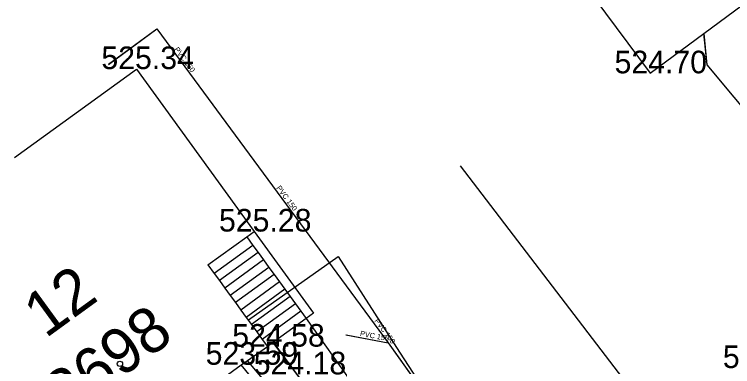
# Model space of a CAD drawing. Extents: x -668867 to -667827, y -1131943 to -1131019.
# Drawn here: x -668667.52 to -668643.7, y -1131500.87 to -1131489.18 of the extents above; entities that cross this region are included whole.
import ezdxf

# ---------------------------------------------------------------- set-up
doc = ezdxf.new("R2010")
doc.units = 0
for name, color, linetype in [('G_Bod_tecka', 7, 'Continuous'), ('G_Bod_vyska', 7, 'Continuous'), ('G_Budovy-znacky', 7, 'Continuous'), ('G_Budovy_Objekty', 7, 'Continuous'), ('G_Budovy_vstupy', 7, 'Continuous'), ('G_Cesty_Schody', 7, 'Continuous'), ('G_Cisla_orientacni', 7, 'Continuous'), ('G_Cisla_popisna', 7, 'Continuous'), ('G_Plochy_zpevnene', 7, 'Continuous'), ('G_Ploty', 7, 'Continuous'), ('G_Z_KANAL_podz_kotovane', 7, 'Continuous'), ('G_Z_KANAL_podz_priblizne', 7, 'Continuous'), ('G_Z_SPOJE_podz_geodeticky', 7, 'Continuous'), ('G_Z_SPOJE_podz_kotovane', 7, 'Continuous'), ('G_Z_SPOJE_podz_priblizne', 7, 'Continuous'), ('G_Z_VODA_podz_kotovane', 7, 'Continuous'), ('Vrstva 12', 7, 'Continuous'), ('Vrstva 17', 7, 'Continuous'), ('Vrstva 25', 7, 'Continuous'), ('Vrstva 3', 7, 'Continuous')]:
    doc.layers.add(name, color=color, linetype=linetype)

msp = doc.modelspace()

# ---------------------------------------------------------------- linework, layer by layer
at = {"layer": 'G_Bod_tecka'}
for p, q in [((-668663.47, -1131491), (-668663.47, -1131491)), ((-668646.43, -1131491.14), (-668646.43, -1131491.14)), ((-668659.57, -1131496.39), (-668659.57, -1131496.39)), ((-668659.13, -1131500.21), (-668659.13, -1131500.21)), ((-668660.01, -1131500.81), (-668660.01, -1131500.81))]:
    msp.add_line(p, q, dxfattribs=at)
at = {"layer": 'G_Budovy-znacky'}
msp.add_circle((-668664.02, -1131500.78), 0.0875, dxfattribs=at)
at = {"layer": 'G_Budovy_Objekty'}
for p, q in [((-668649.42, -1131487.12), (-668646.43, -1131491.14)), ((-668646.43, -1131491.14), (-668643.03, -1131488.6)), ((-668667.52, -1131493.93), (-668663.47, -1131491)), ((-668663.47, -1131491), (-668659.57, -1131496.39)), ((-668661.1, -1131497.5), (-668659.81, -1131496.57)), ((-668659.81, -1131496.57), (-668659.57, -1131496.39)), ((-668661.1, -1131497.5), (-668660.89, -1131497.78)), ((-668660.89, -1131497.78), (-668660.72, -1131498.02)), ((-668660.72, -1131498.02), (-668660.54, -1131498.27)), ((-668660.54, -1131498.27), (-668660.36, -1131498.51)), ((-668660.36, -1131498.51), (-668660.19, -1131498.75)), ((-668660.19, -1131498.75), (-668660.01, -1131499)), ((-668660.01, -1131499), (-668659.83, -1131499.24)), ((-668659.83, -1131499.24), (-668659.66, -1131499.48)), ((-668659.66, -1131499.48), (-668659.48, -1131499.72)), ((-668659.48, -1131499.72), (-668659.3, -1131499.97)), ((-668659.3, -1131499.97), (-668659.13, -1131500.21)), ((-668659.79, -1131500.67), (-668659.13, -1131500.21)), ((-668660, -1131500.81), (-668659.79, -1131500.67))]:
    msp.add_line(p, q, dxfattribs=at)
at = {"layer": 'G_Budovy_vstupy'}
msp.add_line((-668661.98, -1131502.26), (-668660, -1131500.81), dxfattribs=at)
at = {"layer": 'G_Cesty_Schody'}
for p, q in [((-668659.81, -1131496.57), (-668659.61, -1131496.85)), ((-668659.57, -1131496.39), (-668657.6, -1131499.1)), ((-668659.61, -1131496.85), (-668660.89, -1131497.78)), ((-668659.61, -1131496.85), (-668659.43, -1131497.09)), ((-668659.43, -1131497.09), (-668660.72, -1131498.02)), ((-668659.43, -1131497.09), (-668659.26, -1131497.33)), ((-668659.26, -1131497.33), (-668660.54, -1131498.27)), ((-668659.26, -1131497.33), (-668659.08, -1131497.58)), ((-668659.08, -1131497.58), (-668660.36, -1131498.51)), ((-668659.08, -1131497.58), (-668658.9, -1131497.82)), ((-668658.9, -1131497.82), (-668660.19, -1131498.75)), ((-668658.9, -1131497.82), (-668658.73, -1131498.06)), ((-668658.73, -1131498.06), (-668660.01, -1131499)), ((-668658.73, -1131498.06), (-668658.55, -1131498.3)), ((-668658.55, -1131498.3), (-668659.83, -1131499.24)), ((-668658.55, -1131498.3), (-668658.37, -1131498.55)), ((-668658.37, -1131498.55), (-668659.66, -1131499.48)), ((-668658.37, -1131498.55), (-668658.2, -1131498.79)), ((-668658.2, -1131498.79), (-668659.48, -1131499.72)), ((-668658.2, -1131498.79), (-668658.02, -1131499.03)), ((-668658.02, -1131499.03), (-668659.3, -1131499.97)), ((-668658.02, -1131499.03), (-668657.84, -1131499.28)), ((-668657.6, -1131499.1), (-668657.84, -1131499.28)), ((-668657.84, -1131499.28), (-668659.13, -1131500.21))]:
    msp.add_line(p, q, dxfattribs=at)
at = {"layer": 'G_Plochy_zpevnene'}
for p, q in [((-668657.84, -1131499.28), (-668651.99, -1131507.5)), ((-668659.25, -1131501.71), (-668660, -1131500.81)), ((-668659.25, -1131501.32), (-668659.79, -1131500.67))]:
    msp.add_line(p, q, dxfattribs=at)
at = {"layer": 'G_Ploty'}
msp.add_line((-668646.1, -1131502.88), (-668652.73, -1131494.21), dxfattribs=at)
at = {"layer": 'G_Z_KANAL_podz_kotovane'}
msp.add_line((-668656.52, -1131499.82), (-668655.12, -1131500.08), dxfattribs=at)
msp.add_lwpolyline([(-668664.4, -1131490.84), (-668662.8, -1131489.66), (-668655.12, -1131500.08), (-668650.54, -1131506.52)], dxfattribs=at)
at = {"layer": 'G_Z_KANAL_podz_priblizne'}
msp.add_lwpolyline([(-668644.66, -1131489.82), (-668644.55, -1131490.86), (-668640.92, -1131495.22), (-668640.78, -1131496), (-668639.75, -1131497.44)], dxfattribs=at)
at = {"layer": 'G_Z_SPOJE_podz_geodeticky'}
msp.add_lwpolyline([(-668659.76, -1131499.32), (-668656.78, -1131497.22), (-668654.75, -1131500.39), (-668650.81, -1131506.44), (-668650.86, -1131507.14), (-668653.05, -1131508.79), (-668656.45, -1131511.14), (-668656.9, -1131511.45), (-668657.68, -1131511.93), (-668658.58, -1131512.67), (-668663.292, -1131516.083)], dxfattribs=at)
at = {"layer": 'G_Z_SPOJE_podz_kotovane'}
msp.add_lwpolyline([(-668659.76, -1131499.32), (-668656.78, -1131497.22), (-668654.75, -1131500.39), (-668650.81, -1131506.44), (-668650.86, -1131507.14), (-668653.05, -1131508.79), (-668656.45, -1131511.14), (-668656.9, -1131511.45), (-668657.68, -1131511.93), (-668658.58, -1131512.67), (-668663.292, -1131516.083)], dxfattribs=at)
at = {"layer": 'G_Z_SPOJE_podz_priblizne'}
msp.add_lwpolyline([(-668659.76, -1131499.32), (-668656.78, -1131497.22), (-668654.75, -1131500.39), (-668650.81, -1131506.44), (-668650.86, -1131507.14), (-668653.05, -1131508.79), (-668656.45, -1131511.14), (-668656.9, -1131511.45), (-668657.68, -1131511.93), (-668658.58, -1131512.67), (-668663.292, -1131516.083)], dxfattribs=at)
at = {"layer": 'G_Z_VODA_podz_kotovane'}
msp.add_line((-668652.56, -1131508.63), (-668658.91, -1131500.1), dxfattribs=at)
at = {"layer": 'Vrstva 12'}
msp.add_line((-668656.525, -1131499.821), (-668655.12, -1131500.08), dxfattribs=at)
msp.add_lwpolyline([(-668664.398, -1131490.842), (-668662.8, -1131489.66), (-668655.12, -1131500.08), (-668650.544, -1131506.524)], dxfattribs=at)
at = {"layer": 'Vrstva 17'}
msp.add_lwpolyline([(-668644.661, -1131489.817), (-668644.55, -1131490.86), (-668640.92, -1131495.22), (-668640.78, -1131496), (-668639.75, -1131497.44)], dxfattribs=at)
msp.add_lwpolyline([(-668644.661, -1131489.817), (-668644.55, -1131490.86), (-668640.92, -1131495.22), (-668640.78, -1131496), (-668639.75, -1131497.44)], dxfattribs=at)
at = {"layer": 'Vrstva 25'}
msp.add_line((-668652.565, -1131508.632), (-668658.907, -1131500.096), dxfattribs=at)

# ---------------------------------------------------------------- texts
at = {"layer": 'G_Bod_vyska'}
for s, p in [('525.34', (-668664.634, -1131491)), ('524.70', (-668647.616, -1131491.14)), ('525.28', (-668660.734, -1131496.39)), ('524.58', (-668660.294, -1131500.21)), ('523.59', (-668661.176, -1131500.81)), ('523.57', (-668644.024, -1131500.92)), ('524.18', (-668659.582, -1131501.13))]:
    msp.add_text(s, height=0.75, dxfattribs=at).set_placement(p)
at = {"layer": 'G_Cisla_orientacni'}
msp.add_text('12', height=1.5, rotation=36.0151, dxfattribs=at).set_placement((-668666.485, -1131499.952))
at = {"layer": 'G_Cisla_popisna'}
msp.add_text('3698', height=1.5, rotation=36.0151, dxfattribs=at).set_placement((-668665.786, -1131502.571))
at = {"layer": 'Vrstva 3'}
for rotation, p in [(306.3973, (-668662.227, -1131490.348)), (306.4247, (-668658.84, -1131494.944)), (306.3973, (-668655.588, -1131499.355)), (349.5704, (-668656.067, -1131499.852))]:
    msp.add_text('PVC 150', height=0.1755, rotation=rotation, dxfattribs=at).set_placement(p)

doc.saveas('drawing.dxf')
